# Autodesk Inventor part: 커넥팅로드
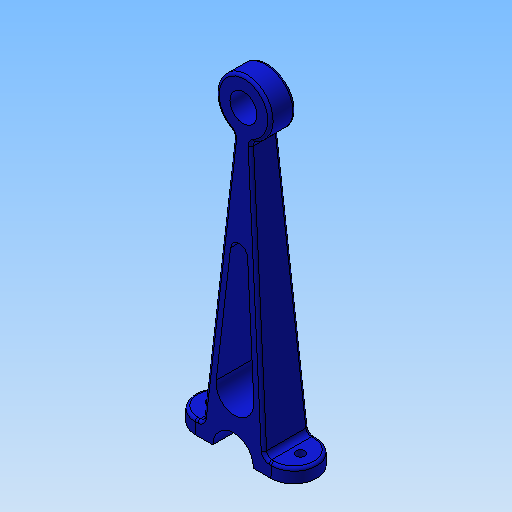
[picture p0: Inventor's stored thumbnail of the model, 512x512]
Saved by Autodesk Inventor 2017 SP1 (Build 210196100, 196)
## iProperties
Created: 2017-05
Part Number: 커넥팅로드
Material: 강철, 탄소
Document SubType Name: Modeling
Designer: mduedu
Density: 7.87 g/cm^3
Mass: 120.522 g
Surface Area: 85.3879 cm^2
Volume: 15.3141 cm^3
Appearance: 파란색 - 벽 페인트 - 무광
Author: mduedu
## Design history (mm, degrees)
sketch "스케치1"
  geometry: L1 (-22.5, 0)-(22.5, 0); L2 (22.5, 0)-(22.5, 5); L3 (-22.5, 5)-(-22.5, 0); L4 (-11.352, 5)-(-3, 100.461); L5 (0, 110)-(0, 0); L6 (11.352, 5)-(3, 100.461); L7 (22.5, 5)-(11.352, 5); L8 (-11.352, 5)-(-22.5, 5); C1 r 5 at (0, 110); A1 r 10 centre (0, 110) between (3, 100.461) and (-3, 100.461); 1 further point
  constraints: 16 end point, 4 parallel, 2 centre point, 2 coincident, 2 point on circle, 2 symmetric about line, 1 horizontal, 1 midpoint, 1 perpendicular, 1 vertical alignment
  dimensions: "d0" = 5 distance of L1.end L2.end; "d2" = 45 distance of L1.start L1.end; "d3" = 20 diameter of A1; "d4" = 10 diameter of C1; "d5" = 110 distance from line of L1 L5.start; "d6" = 5 deg angle of L5 L4; "d7" = 3 distance from line of L4.end L5
extrude "돌출1" new body sketch "스케치1" distance "d8" = 8.5; taper "d9" = 0 deg
sketch "스케치2"
  geometry: C1 r 7.5 at (0, 0); 1 further point
  constraints: 1 centre point, 1 coincident
  dimensions: "d10" = 15 diameter of C1
extrude "돌출2" cut sketch "스케치2" stored distance "d11" = 8.5; taper "d12" = 0 deg
sketch "스케치3"
  geometry: L1 (-3, 100.461)-(-11.352, 5) reference; L2 (11.352, 5)-(3, 100.461) reference; L3 (-3.154, 64.276)-(-6.975, 20.61); L4 (6.975, 20.61)-(3.154, 64.276); A1 r 3.166 centre (0, 64) between (3.154, 64.276) and (-3.154, 64.276); A2 r 7.001 centre (0, 20) between (-6.975, 20.61) and (6.975, 20.61); 1 further point
  constraints: 4 end point, 4 point on circle, 4 tangent, 2 centre point, 2 parallel, 1 vertical alignment
  dimensions: "d15" = 3 distance between parallel lines of L2 L4; "d16" = 44 distance of A2.centre A1.centre; "d17" = 20 distance of A2.centre point (0, 0)
extrude "돌출3" cut sketch "스케치3" stored distance "d18" = 8.5; taper "d19" = 0 deg
fillet "모깎기1" dims "d20" = 2
fillet "모깎기2" dims "d21" = 2
feature "면 기울기1" dims angle "d22" = 2 deg
fillet "모깎기3"
fillet "모깎기4"
fillet "모깎기5" dims "d28" = 1
sketch "스케치5"
  geometry: 3 further points
  constraints: 2 horizontal alignment
  dimensions: "d29" = 16.5 distance of point (-2.364, -7.36) point (14.136, -7.36); "d30" = 16.5 distance of point (30.636, -7.36) point (14.136, -7.36) (= d29)
sketch "스케치6"
  geometry: 2 further points
  constraints: 2 other
hole "구멍1" sketch "스케치6" at (-29.684, -7.36), (3.316, -7.36) diameter "d31" = 3.4; stored, may be unused: countersink angle "d35" = 90 deg, drill point angle "d37" = 0 deg; dims "d32" = 6, "d33" = 4, "d34" = 2, "d36" = 8
node "솔리드1"
mirror "대칭1"
other parameters: "d13" = 4, "d14" = 4
